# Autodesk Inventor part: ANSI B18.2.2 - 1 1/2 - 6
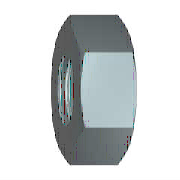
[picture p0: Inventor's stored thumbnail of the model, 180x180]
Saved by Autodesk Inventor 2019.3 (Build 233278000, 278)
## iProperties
Created: 2018-01
Part Number: ANSI B18.2.2 - 1 1/2 - 6
Material: Steel, Mild
Description: Hex Nuts (Inch Series) Heavy Hex Nut
Document SubType Name: Modeling
Standard: ANSI B18.2.2
Designer: u1426
Standard Revision: 2010
Standards Organization: ANSI
Language: en-US
Size Designation: 1 1/2 - 6
Categories: <MemberInstance><Categories><Category DisplayName="Fasteners" InternalName="e4da775c-781d-43d5-af7c-5136215cf5a6" Mnemonic="FSTN"><Category DisplayName="Nuts" I
Density: 7.85 g/cm^3
Appearance: Semi-Polished
IsCustomPart: 0
Author: u1426
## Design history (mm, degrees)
sketch "Sketch1"
  geometry: L1 (-34.829, 0)-(-17.414, 30.163); L2 (-17.414, 30.163)-(17.414, 30.163); L3 (17.414, 30.163)-(34.829, 0); L4 (34.829, 0)-(17.414, -30.162); L5 (17.414, -30.162)-(-17.414, -30.163); L6 (-17.414, -30.163)-(-34.829, 0); 2 further points
  constraints: 12 end point, 1 coincident, 1 horizontal, 11 other
  dimensions: "d0" = 69.65731 distance of L3.end L1.start (= 1.1547 x SW)
extrude "Body" new body sketch "Sketch1" distance "d1" = 37.3126 (= KOH); taper "d2" = 0 deg
sketch "Sketch2"
  geometry: L1 (0, 17.414)-(0, 34.829) reference; L2 (0, 34.829)-(37.313, 34.829) reference; L3 (37.313, 17.414)-(37.313, 34.829) reference; L4 (-7.463, 0)-(44.775, 0) reference; L5 (2.176, 34.829)-(0, 30.162); L6 (35.137, 34.829)-(37.313, 30.162)
  constraints: 4 end point, 4 point on line
  dimensions: "d3" = 25 deg angle of L1 L5 (= ANG1); "d4" = 25 deg angle of L3 L6 (= ANG2); "d5" = 60.325 diameter of L5.end L4 (= SW0); "d6" = 60.325 diameter of L6.end L4 (= SW01)
revolve "Chamfer1" sketch "Sketch2" stored, may be unused: angle "d7" = 90 deg
sketch "Sketch3"
  geometry: A1 r 30.163 centre (0, 0) between (-15.081, -26.121) and (15.081, -26.121) reference; 1 further point
  constraints: 1 coincident
hole "Thread" sketch "Sketch3" at (0, 0) diameter "d25" = 33.528; stored, may be unused: countersink angle "d29" = 82 deg, drill point angle "d31" = 118 deg; dims "d26" = 6, "d27" = 4, "d28" = 2, "d30" = 8
workaxis "Work Axis1"
workplane "Work Plane1"
body "Solid1"
chamfer "Chamfer2" distance "d8" = 2.29136 (= -0.5 x GD1 + 0.5 x NND); stored, may be unused: angle "d9" = 30 deg, second distance "d40" = 2.29136 (= -0.5 x GD1 + 0.5 x NND)
chamfer "Chamfer3" distance "d10" = 2.29136 (= -0.5 x GD1 + 0.5 x NND); stored, may be unused: angle "d11" = 30 deg, second distance "d41" = 2.29136 (= -0.5 x GD1 + 0.5 x NND)
other parameters: "ANG1" = 25 deg [user parameter; used in 1 equation term], "ANG2" = 25 deg [user parameter; used in 1 equation term], "NND" = 38.1 [user parameter; used in 4 equation terms], "KOH" = 37.3126 [user parameter; used in 1 equation term], "SW" = 60.325 [user parameter; used in 4 equation terms], "SW0" = 60.325 (= SW) [user parameter; used in 1 equation term], "SW01" = 60.325 (= SW) [user parameter; used in 1 equation term], "GD1" = 33.51728 (computed from THREADDIA, PTC, TOA) [user parameter; used in 4 equation terms], "d13" = 0, "d14" = 0, "d39" = 0, "d42" = 0, "THREADDIA" = 38.1 [user parameter; used in 1 equation term], "TOA" = 30 deg [user parameter; used in 1 equation term], "PTC" = 4.23333 (computed from TPU) [user parameter; used in 1 equation term], "E0" = 69.67538 (= 1.155 x SW) [user parameter]
